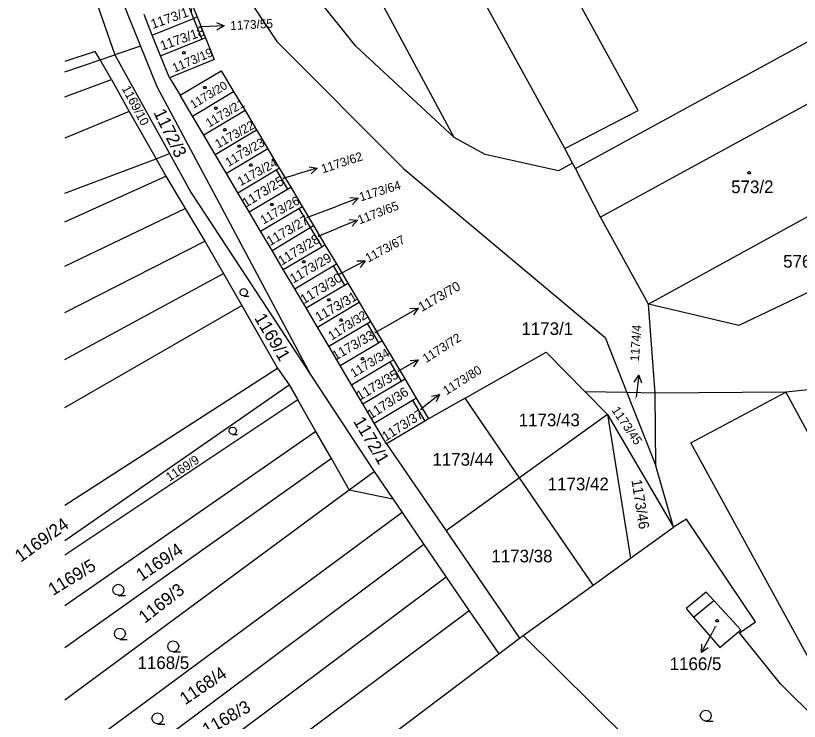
# Model space of a CAD drawing. Extents: x -621797 to -620972, y -1175539 to -1174697.
# Drawn here: x -621796.9 to -621691.5, y -1174979.5 to -1174884.6 of the extents above; entities that cross this region are included whole.
import ezdxf

# ---------------------------------------------------------------- set-up
doc = ezdxf.new("R2010")
doc.units = 0
for name, color, linetype in [('INZ mimo EON - nadz', 7, 'Continuous'), ('Rozvod plynu EON', 7, 'Continuous'), ('SDEL EON', 7, 'Continuous'), ('SDEL EON - popis', 7, 'Continuous'), ('Silnoproud EON', 7, 'Continuous'), ('Silnoproud EON - popis', 7, 'Continuous')]:
    doc.layers.add(name, color=color, linetype=linetype)

msp = doc.modelspace()

# ---------------------------------------------------------------- linework, layer by layer
at = {"layer": 'INZ mimo EON - nadz'}
for p, q in [((-621772.32, -1174886.11), (-621771.91, -1174886.09)), ((-621768.913, -1174885.959), (-621771.91, -1174886.09)), ((-621756.383, -1174905.079), (-621759.26, -1174905.93)), ((-621760.98, -1174906.44), (-621759.26, -1174905.93)), ((-621750.883, -1174909.131), (-621753.69, -1174910.19)), ((-621757.77, -1174911.73), (-621753.69, -1174910.19)), ((-621750.968, -1174912.062), (-621753.74, -1174913.21)), ((-621756.24, -1174914.24), (-621753.74, -1174913.21)), ((-621749.947, -1174917.538), (-621752.61, -1174918.92)), ((-621753.37, -1174919.31), (-621752.61, -1174918.92)), ((-621742.792, -1174923.898), (-621745.4, -1174925.38)), ((-621748.6, -1174927.19), (-621745.4, -1174925.38)), ((-621742.784, -1174930.881), (-621745.4, -1174932.35)), ((-621745.5, -1174932.4), (-621745.4, -1174932.35)), ((-621713.134, -1174932.922), (-621713.5, -1174935.9)), ((-621739.916, -1174935.52), (-621742.27, -1174937.38)), ((-621742.47, -1174937.53), (-621742.27, -1174937.38)), ((-621702.85, -1174966.79), (-621703.28, -1174967.6)), ((-621704.699, -1174970.243), (-621703.28, -1174967.6))]:
    msp.add_line(p, q, dxfattribs=at)
for points in [[(-621769.934, -1174885.503), (-621768.913, -1174885.959), (-621769.89, -1174886.502)], [(-621757.484, -1174904.883), (-621756.383, -1174905.079), (-621757.2, -1174905.842)], [(-621751.995, -1174909.016), (-621750.883, -1174909.131), (-621751.642, -1174909.952)], [(-621752.083, -1174911.983), (-621750.968, -1174912.062), (-621751.701, -1174912.907)], [(-621751.065, -1174917.555), (-621749.947, -1174917.538), (-621750.604, -1174918.443)], [(-621743.908, -1174923.957), (-621742.792, -1174923.898), (-621743.414, -1174924.827)], [(-621743.901, -1174930.935), (-621742.784, -1174930.881), (-621743.411, -1174931.807)], [(-621713.753, -1174933.854), (-621713.134, -1174932.922), (-621712.76, -1174933.976)], [(-621741.011, -1174935.748), (-621739.916, -1174935.52), (-621740.391, -1174936.533)], [(-621703.785, -1174969.599), (-621704.699, -1174970.243), (-621704.666, -1174969.126)]]:
    msp.add_lwpolyline(points, dxfattribs=at)
at = {"layer": 'Rozvod plynu EON'}
for points in [[(-621774.22, -1174889.41), (-621774.13, -1174889.56), (-621774.22, -1174889.71), (-621774.4, -1174889.71), (-621774.49, -1174889.56), (-621774.4, -1174889.41)], [(-621771.42, -1174894.08), (-621771.33, -1174894.23), (-621771.42, -1174894.38), (-621771.6, -1174894.38), (-621771.69, -1174894.23), (-621771.6, -1174894.08)], [(-621769.92, -1174896.87), (-621769.83, -1174897.02), (-621769.92, -1174897.17), (-621770.1, -1174897.17), (-621770.19, -1174897.02), (-621770.1, -1174896.87)], [(-621768.71, -1174899.77), (-621768.62, -1174899.92), (-621768.71, -1174900.07), (-621768.89, -1174900.07), (-621768.98, -1174899.92), (-621768.89, -1174899.77)], [(-621766.8, -1174901.97), (-621766.71, -1174902.12), (-621766.8, -1174902.27), (-621766.98, -1174902.27), (-621767.07, -1174902.12), (-621766.98, -1174901.97)], [(-621765.23, -1174904.51), (-621765.14, -1174904.66), (-621765.23, -1174904.81), (-621765.41, -1174904.81), (-621765.5, -1174904.66), (-621765.41, -1174904.51)], [(-621698.19, -1174905.54), (-621698.1, -1174905.69), (-621698.19, -1174905.84), (-621698.37, -1174905.84), (-621698.46, -1174905.69), (-621698.37, -1174905.54)], [(-621762.38, -1174909.82), (-621762.29, -1174909.97), (-621762.38, -1174910.12), (-621762.56, -1174910.12), (-621762.65, -1174909.97), (-621762.56, -1174909.82)], [(-621758.07, -1174917.52), (-621757.98, -1174917.67), (-621758.07, -1174917.82), (-621758.25, -1174917.82), (-621758.34, -1174917.67), (-621758.25, -1174917.52)], [(-621754.71, -1174922.64), (-621754.62, -1174922.79), (-621754.71, -1174922.94), (-621754.89, -1174922.94), (-621754.98, -1174922.79), (-621754.89, -1174922.64)], [(-621753.06, -1174925.36), (-621752.97, -1174925.51), (-621753.06, -1174925.66), (-621753.24, -1174925.66), (-621753.33, -1174925.51), (-621753.24, -1174925.36)], [(-621750.21, -1174930.56), (-621750.12, -1174930.71), (-621750.21, -1174930.86), (-621750.39, -1174930.86), (-621750.48, -1174930.71), (-621750.39, -1174930.56)], [(-621702.5, -1174965.81), (-621702.41, -1174965.96), (-621702.5, -1174966.11), (-621702.68, -1174966.11), (-621702.77, -1174965.96), (-621702.68, -1174965.81)]]:
    msp.add_lwpolyline(points, close=True, dxfattribs=at)
at = {"layer": 'SDEL EON'}
for points in [[(-621766.25, -1174922.27), (-621766.505, -1174922.203), (-621766.686, -1174922.022), (-621766.752, -1174921.774), (-621766.686, -1174921.526), (-621766.505, -1174921.345), (-621766.257, -1174921.278), (-621766.009, -1174921.345), (-621765.828, -1174921.526), (-621765.761, -1174921.781), (-621765.828, -1174922.036), (-621766.009, -1174922.216), (-621766.263, -1174922.283), (-621765.593, -1174922.283)], [(-621767.74, -1174940.9), (-621767.995, -1174940.833), (-621768.176, -1174940.652), (-621768.242, -1174940.404), (-621768.176, -1174940.156), (-621767.995, -1174939.975), (-621767.747, -1174939.908), (-621767.499, -1174939.975), (-621767.318, -1174940.156), (-621767.251, -1174940.411), (-621767.318, -1174940.666), (-621767.499, -1174940.846), (-621767.753, -1174940.913), (-621767.083, -1174940.913)], [(-621783.12, -1174962.54), (-621783.5, -1174962.44), (-621783.77, -1174962.17), (-621783.87, -1174961.8), (-621783.77, -1174961.43), (-621783.5, -1174961.16), (-621783.13, -1174961.06), (-621782.76, -1174961.16), (-621782.49, -1174961.43), (-621782.39, -1174961.81), (-621782.49, -1174962.19), (-621782.76, -1174962.46), (-621783.14, -1174962.56), (-621782.14, -1174962.56)], [(-621782.91, -1174968.45), (-621783.29, -1174968.35), (-621783.56, -1174968.08), (-621783.66, -1174967.71), (-621783.56, -1174967.34), (-621783.29, -1174967.07), (-621782.92, -1174966.97), (-621782.55, -1174967.07), (-621782.28, -1174967.34), (-621782.18, -1174967.72), (-621782.28, -1174968.1), (-621782.55, -1174968.37), (-621782.93, -1174968.47), (-621781.93, -1174968.47)], [(-621775.74, -1174970.14), (-621776.12, -1174970.04), (-621776.39, -1174969.77), (-621776.49, -1174969.4), (-621776.39, -1174969.03), (-621776.12, -1174968.76), (-621775.75, -1174968.66), (-621775.38, -1174968.76), (-621775.11, -1174969.03), (-621775.01, -1174969.41), (-621775.11, -1174969.79), (-621775.38, -1174970.06), (-621775.76, -1174970.16), (-621774.76, -1174970.16)], [(-621777.85, -1174979.84), (-621778.23, -1174979.74), (-621778.5, -1174979.47), (-621778.6, -1174979.1), (-621778.5, -1174978.73), (-621778.23, -1174978.46), (-621777.86, -1174978.36), (-621777.49, -1174978.46), (-621777.22, -1174978.73), (-621777.12, -1174979.11), (-621777.22, -1174979.49), (-621777.49, -1174979.76), (-621777.87, -1174979.86), (-621776.87, -1174979.86)], [(-621704.12, -1174979.46), (-621704.5, -1174979.36), (-621704.77, -1174979.09), (-621704.87, -1174978.72), (-621704.77, -1174978.35), (-621704.5, -1174978.08), (-621704.13, -1174977.98), (-621703.76, -1174978.08), (-621703.49, -1174978.35), (-621703.39, -1174978.73), (-621703.49, -1174979.11), (-621703.76, -1174979.38), (-621704.14, -1174979.48), (-621703.14, -1174979.48)]]:
    msp.add_lwpolyline(points, dxfattribs=at)
at = {"layer": 'SDEL EON - popis'}
for p, q in [((-621713.24, -1174897.34), (-621756.56, -1174818.04)), ((-621786.26, -1174889.38), (-621790.31, -1174890.72)), ((-621785.59, -1174890.53), (-621786.26, -1174889.38)), ((-621683.62, -1174892.74), (-621718.27, -1174911.66)), ((-621723.06, -1174902.46), (-621713.24, -1174897.34)), ((-621706.15, -1174942.05), (-621693.38, -1174935.2)), ((-621693.38, -1174935.2), (-621666.02, -1174985.69)), ((-621688.4, -1174974.48), (-621706.15, -1174942.05)), ((-621752.08, -1174948.35), (-621746.22, -1174949.57)), ((-621705.76, -1174965.48), (-621703.03, -1174963.24))]:
    msp.add_line(p, q, dxfattribs=at)
at = {"layer": 'Silnoproud EON'}
for p, q in [((-621723.06, -1174902.46), (-621766.48, -1174823.5)), ((-621737.97, -1174900.96), (-621773.9, -1174834.07)), ((-621790.31, -1174863.397), (-621780.14, -1174888.68)), ((-621790.31, -1174870.521), (-621783.6, -1174889.85)), ((-621772.95, -1174871.4), (-621761.8, -1174888.04)), ((-621751.2, -1174888.69), (-621762.62, -1174874.29)), ((-621774.11, -1174882.15), (-621773, -1174884.93)), ((-621773.66, -1174881.96), (-621772.54, -1174884.74)), ((-621778.56, -1174887.19), (-621779.67, -1174884.4)), ((-621778.56, -1174887.19), (-621773, -1174884.93)), ((-621773, -1174884.93), (-621772.54, -1174884.74)), ((-621773, -1174884.93), (-621771.88, -1174887.72)), ((-621772.54, -1174884.74), (-621771.42, -1174887.53)), ((-621721.67, -1174905.13), (-621687.14, -1174886.26)), ((-621777.44, -1174889.97), (-621778.56, -1174887.19)), ((-621777.44, -1174889.97), (-621771.88, -1174887.72)), ((-621771.88, -1174887.72), (-621771.42, -1174887.53)), ((-621771.42, -1174887.53), (-621770.24, -1174890.46)), ((-621780.14, -1174888.68), (-621783.6, -1174889.85)), ((-621780.14, -1174888.68), (-621777.95, -1174894.12)), ((-621761.8, -1174888.04), (-621744.73, -1174905.18)), ((-621737.97, -1174900.96), (-621751.2, -1174888.69)), ((-621785.59, -1174890.53), (-621783.6, -1174889.85)), ((-621783.6, -1174889.85), (-621776.23, -1174903.12)), ((-621790.31, -1174892.134), (-621785.59, -1174890.53)), ((-621784.06, -1174893.17), (-621785.59, -1174890.53)), ((-621776.26, -1174892.92), (-621777.44, -1174889.97)), ((-621770.24, -1174890.46), (-621776.26, -1174892.92)), ((-621774.82, -1174895.27), (-621769.28, -1174891.97)), ((-621769.28, -1174891.97), (-621767.62, -1174894.77)), ((-621776.26, -1174892.92), (-621774.82, -1174895.27)), ((-621790.31, -1174895.476), (-621784.06, -1174893.17)), ((-621784.06, -1174893.17), (-621781.69, -1174897.47)), ((-621777.95, -1174894.12), (-621769.94, -1174909.12)), ((-621773.16, -1174898.07), (-621767.62, -1174894.77)), ((-621767.62, -1174894.77), (-621766.08, -1174897.34)), ((-621773.16, -1174898.07), (-621774.82, -1174895.27)), ((-621781.69, -1174897.47), (-621790.31, -1174901.046)), ((-621781.69, -1174897.47), (-621778.06, -1174903.81)), ((-621771.64, -1174900.65), (-621773.16, -1174898.07)), ((-621766.08, -1174897.34), (-621771.64, -1174900.65)), ((-621766.08, -1174897.34), (-621764.55, -1174899.92)), ((-621770.11, -1174903.23), (-621764.55, -1174899.92)), ((-621764.55, -1174899.92), (-621763.01, -1174902.5)), ((-621770.11, -1174903.23), (-621771.64, -1174900.65)), ((-621733.78, -1174903.26), (-621737.97, -1174900.96)), ((-621763.01, -1174902.5), (-621768.58, -1174905.81)), ((-621763.01, -1174902.5), (-621761.48, -1174905.08)), ((-621722.05, -1174904.4), (-621723.06, -1174902.46)), ((-621778.06, -1174903.81), (-621776.23, -1174903.12)), ((-621776.23, -1174903.12), (-621773.32, -1174908.38)), ((-621768.58, -1174905.81), (-621770.11, -1174903.23)), ((-621723.95, -1174905.43), (-621733.78, -1174903.26)), ((-621790.31, -1174908.448), (-621778.06, -1174903.81)), ((-621778.06, -1174903.81), (-621776.73, -1174906.14)), ((-621722.05, -1174904.4), (-621723.95, -1174905.43)), ((-621721.67, -1174905.13), (-621722.05, -1174904.4)), ((-621677.24, -1174904.34), (-621711.84, -1174923.39)), ((-621767.05, -1174908.39), (-621761.89, -1174905.33)), ((-621761.89, -1174905.33), (-621761.48, -1174905.08)), ((-621761.89, -1174905.33), (-621760.37, -1174907.91)), ((-621761.48, -1174905.08), (-621759.95, -1174907.66)), ((-621744.73, -1174905.18), (-621717.67, -1174927.85)), ((-621718.27, -1174911.66), (-621721.67, -1174905.13)), ((-621790.31, -1174912.295), (-621776.73, -1174906.14)), ((-621776.73, -1174906.14), (-621774.16, -1174910.52)), ((-621767.05, -1174908.39), (-621768.58, -1174905.81)), ((-621760.37, -1174907.91), (-621759.95, -1174907.66)), ((-621759.95, -1174907.66), (-621758.41, -1174910.24)), ((-621773.32, -1174908.38), (-621757.24, -1174932.92)), ((-621765.52, -1174910.97), (-621767.05, -1174908.39)), ((-621765.52, -1174910.97), (-621760.37, -1174907.91)), ((-621769.94, -1174909.12), (-621757.24, -1174932.92)), ((-621790.31, -1174918.28), (-621774.16, -1174910.52)), ((-621774.16, -1174910.52), (-621771.5, -1174914.91)), ((-621763.99, -1174913.56), (-621765.52, -1174910.97)), ((-621763.99, -1174913.56), (-621758.84, -1174910.49)), ((-621758.84, -1174910.49), (-621758.41, -1174910.24)), ((-621758.84, -1174910.49), (-621757.31, -1174913.07)), ((-621758.41, -1174910.24), (-621756.88, -1174912.81)), ((-621711.84, -1174923.39), (-621718.27, -1174911.66)), ((-621762.46, -1174916.14), (-621757.31, -1174913.07)), ((-621757.31, -1174913.07), (-621756.88, -1174912.81)), ((-621757.31, -1174913.07), (-621755.78, -1174915.65)), ((-621756.88, -1174912.81), (-621755.34, -1174915.39)), ((-621762.46, -1174916.14), (-621763.99, -1174913.56)), ((-621790.31, -1174924.516), (-621771.5, -1174914.91)), ((-621771.5, -1174914.91), (-621768.97, -1174919.27)), ((-621676.24, -1174915.04), (-621699.69, -1174926.23)), ((-621760.94, -1174918.72), (-621762.46, -1174916.14)), ((-621760.94, -1174918.72), (-621755.78, -1174915.65)), ((-621755.78, -1174915.65), (-621755.34, -1174915.39)), ((-621755.34, -1174915.39), (-621753.81, -1174917.97)), ((-621759.41, -1174921.3), (-621754.25, -1174918.23)), ((-621754.25, -1174918.23), (-621753.81, -1174917.97)), ((-621754.25, -1174918.23), (-621752.72, -1174920.81)), ((-621753.81, -1174917.97), (-621752.28, -1174920.55)), ((-621790.31, -1174930.838), (-621768.97, -1174919.27)), ((-621768.97, -1174919.27), (-621766.52, -1174923.57)), ((-621759.41, -1174921.3), (-621760.94, -1174918.72)), ((-621757.88, -1174923.88), (-621759.41, -1174921.3)), ((-621757.88, -1174923.88), (-621752.72, -1174920.81)), ((-621752.72, -1174920.81), (-621752.28, -1174920.55)), ((-621752.28, -1174920.55), (-621750.74, -1174923.13)), ((-621790.31, -1174937.274), (-621766.52, -1174923.57)), ((-621766.52, -1174923.57), (-621761.71, -1174932)), ((-621756.35, -1174926.46), (-621751.19, -1174923.39)), ((-621751.19, -1174923.39), (-621750.74, -1174923.13)), ((-621750.74, -1174923.13), (-621749.21, -1174925.7)), ((-621699.69, -1174926.23), (-621711.84, -1174923.39)), ((-621710.94, -1174935.35), (-621711.84, -1174923.39)), ((-621756.35, -1174926.46), (-621757.88, -1174923.88)), ((-621749.67, -1174925.98), (-621749.21, -1174925.7)), ((-621749.21, -1174925.7), (-621747.67, -1174928.28)), ((-621754.82, -1174929.04), (-621756.35, -1174926.46)), ((-621754.82, -1174929.04), (-621749.67, -1174925.98)), ((-621749.67, -1174925.98), (-621748.14, -1174928.56)), ((-621717.67, -1174927.85), (-621714.75, -1174935.27)), ((-621753.29, -1174931.63), (-621748.14, -1174928.56)), ((-621748.14, -1174928.56), (-621747.67, -1174928.28)), ((-621747.67, -1174928.28), (-621746.14, -1174930.86)), ((-621753.29, -1174931.63), (-621754.82, -1174929.04)), ((-621736.5, -1174936.03), (-621725.58, -1174929.84)), ((-621725.58, -1174929.84), (-621720.37, -1174935.15)), ((-621746.61, -1174931.14), (-621746.14, -1174930.86)), ((-621746.14, -1174930.86), (-621744.61, -1174933.44)), ((-621790.31, -1174950.409), (-621761.71, -1174932)), ((-621761.71, -1174932), (-621760.16, -1174934.22)), ((-621751.77, -1174934.21), (-621753.29, -1174931.63)), ((-621751.77, -1174934.21), (-621746.61, -1174931.14)), ((-621746.61, -1174931.14), (-621745.08, -1174933.72)), ((-621757.24, -1174932.92), (-621748.74, -1174945.88)), ((-621750.24, -1174936.79), (-621745.08, -1174933.72)), ((-621745.08, -1174933.72), (-621744.61, -1174933.44)), ((-621744.61, -1174933.44), (-621743.07, -1174936.02)), ((-621790.31, -1174955.158), (-621760.16, -1174934.22)), ((-621760.16, -1174934.22), (-621759.01, -1174936.23)), ((-621750.24, -1174936.79), (-621751.77, -1174934.21)), ((-621714.75, -1174935.27), (-621720.37, -1174935.15)), ((-621720.37, -1174935.15), (-621717.33, -1174938.24)), ((-621693.38, -1174935.2), (-621710.94, -1174935.35)), ((-621688.39, -1174934.69), (-621693.38, -1174935.2)), ((-621759.01, -1174936.23), (-621790.31, -1174957.145)), ((-621756.56, -1174940.51), (-621759.01, -1174936.23)), ((-621748.71, -1174939.37), (-621743.55, -1174936.3)), ((-621743.55, -1174936.3), (-621743.07, -1174936.02)), ((-621743.55, -1174936.3), (-621741.9, -1174939.1)), ((-621743.07, -1174936.02), (-621741.41, -1174938.81)), ((-621736.5, -1174936.03), (-621741.41, -1174938.81)), ((-621729.17, -1174946.75), (-621736.5, -1174936.03)), ((-621710.94, -1174935.35), (-621714.75, -1174935.27)), ((-621714.75, -1174935.27), (-621710.86, -1174945.13)), ((-621710.86, -1174945.13), (-621710.94, -1174935.35)), ((-621748.71, -1174939.37), (-621750.24, -1174936.79)), ((-621717.33, -1174938.24), (-621729.17, -1174946.75)), ((-621717.33, -1174938.24), (-621708.48, -1174953.39)), ((-621717.33, -1174938.24), (-621714.25, -1174957.55)), ((-621747.05, -1174942.17), (-621748.71, -1174939.37)), ((-621741.9, -1174939.1), (-621747.05, -1174942.17)), ((-621741.41, -1174938.81), (-621741.9, -1174939.1)), ((-621756.56, -1174940.51), (-621790.31, -1174963.977)), ((-621754.47, -1174944.16), (-621756.56, -1174940.51)), ((-621747.05, -1174942.17), (-621739.05, -1174953.85)), ((-621754.47, -1174944.16), (-621790.31, -1174969.598)), ((-621752.08, -1174948.35), (-621754.47, -1174944.16)), ((-621708.48, -1174953.39), (-621710.86, -1174945.13)), ((-621752.08, -1174948.35), (-621748.74, -1174945.88)), ((-621748.74, -1174945.88), (-621746.22, -1174949.57)), ((-621729.17, -1174946.75), (-621739.05, -1174953.85)), ((-621719.29, -1174961.18), (-621729.17, -1174946.75)), ((-621790.31, -1174976.603), (-621752.08, -1174948.35)), ((-621746.22, -1174949.57), (-621744.96, -1174951.42)), ((-621744.96, -1174951.42), (-621790.31, -1174984.913)), ((-621744.96, -1174951.42), (-621742.03, -1174955.71)), ((-621706.74, -1174952.32), (-621708.48, -1174953.39)), ((-621697.46, -1174966.12), (-621706.74, -1174952.32)), ((-621739.05, -1174953.85), (-621729.18, -1174968.32)), ((-621714.25, -1174957.55), (-621708.48, -1174953.39)), ((-621742.03, -1174955.71), (-621790.31, -1174991.795)), ((-621742.03, -1174955.71), (-621739.05, -1174960.08)), ((-621719.29, -1174961.18), (-621714.25, -1174957.55)), ((-621739.05, -1174960.08), (-621790.31, -1174998.498)), ((-621739.05, -1174960.08), (-621735.95, -1174964.61)), ((-621728.68, -1174967.95), (-621719.29, -1174961.18)), ((-621704.06, -1174962.11), (-621706.77, -1174964.31)), ((-621703.03, -1174963.24), (-621704.06, -1174962.11)), ((-621699.4, -1174967.2), (-621703.03, -1174963.24)), ((-621735.95, -1174964.61), (-621790.31, -1175005.233)), ((-621735.95, -1174964.61), (-621731.98, -1174970.42)), ((-621706.77, -1174964.31), (-621705.76, -1174965.48)), ((-621705.76, -1174965.48), (-621702.25, -1174969.58)), ((-621699.58, -1174967.59), (-621697.46, -1174966.12)), ((-621702.25, -1174969.58), (-621699.4, -1174967.2)), ((-621694.08, -1174974.46), (-621699.58, -1174967.59)), ((-621731.98, -1174970.42), (-621729.18, -1174968.32)), ((-621729.18, -1174968.32), (-621728.68, -1174967.95)), ((-621691.74, -1175004.45), (-621728.68, -1174967.95)), ((-621787.64, -1175012.33), (-621731.98, -1174970.42)), ((-621677.59, -1174990.81), (-621694.08, -1174974.46))]:
    msp.add_line(p, q, dxfattribs=at)

# ---------------------------------------------------------------- texts
at = {"layer": 'INZ mimo EON - nadz'}
for s, height, rotation, p in [('1173/55', 1.19, 3.03668, (-621768.045, -1174886.508)), ('1173/62', 1.19, 18.16276, (-621755.618, -1174905.784)), ('1173/64', 1.19, 17.18873, (-621750.524, -1174909.561)), ('1173/65', 1.19, 20.97026, (-621750.671, -1174912.655)), ('1173/67', 1.19, 28.13223, (-621749.515, -1174917.801)), ('1173/70', 1.28, 30.02299, (-621742.335, -1174924.443)), ('1174/4', 1.2, 86.00096, (-621713.121, -1174931.093)), ('1173/72', 1.19, 32.71589, (-621741.731, -1174931.317)), ('1173/80', 1.19, 32.42941, (-621738.991, -1174935.643))]:
    msp.add_text(s, height=height, rotation=rotation, dxfattribs=at).set_placement(p)
msp.add_text('1166/5', height=1.7, dxfattribs=at).set_placement((-621708.983, -1174972.6))
at = {"layer": 'Silnoproud EON - popis'}
for s, height, rotation, p in [('1173/17', 1.28, 19.42327, (-621778.5, -1174886.365)), ('1173/18', 1.28, 19.76704, (-621777.237, -1174889.276)), ('1173/55', 0.1, 293.58357, (-621772.42, -1174885.881)), ('1173/19', 1.19, 23.49127, (-621775.558, -1174892.24)), ('1169/10', 1.2, 297.88076, (-621782.7, -1174894.355)), ('1173/20', 1.14, 31.1689, (-621773.056, -1174897.13)), ('1173/21', 1.19, 30.93972, (-621770.934, -1174899.659)), ('1172/3', 1.7, 296.10459, (-621778.437, -1174897.593)), ('1173/22', 1.19, 28.87707, (-621769.719, -1174902.447)), ('1173/23', 1.2, 30.59595, (-621768.311, -1174904.929)), ('1173/24', 1.2, 28.81978, (-621766.687, -1174907.516)), ('1173/25', 1.28, 31.79916, (-621765.971, -1174910.429)), ('1173/62', 0.1, 301.03202, (-621761.108, -1174906.226)), ('1173/26', 1.19, 29.79381, (-621763.611, -1174912.683)), ('1173/27', 1.28, 30.30947, (-621762.728, -1174915.574)), ('1173/64', 0.1, 296.04729, (-621757.878, -1174911.51)), ('1173/28', 1.28, 31.34079, (-621761.167, -1174918.207)), ('1173/65', 0.1, 299.25586, (-621756.361, -1174914.024)), ('1173/29', 1.27, 30.36676, (-621759.611, -1174920.62)), ('1173/30', 1.28, 31.34079, (-621758.18, -1174923.405)), ('1173/67', 0.1, 302.17794, (-621753.499, -1174919.105)), ('1173/31', 1.27, 29.8511, (-621756.198, -1174925.781)), ('1169/1', 1.7, 300.57366, (-621764.9, -1174925.228)), ('1173/32', 1.2, 32.544, (-621754.436, -1174928.291)), ('1173/33', 1.28, 29.67921, (-621753.927, -1174930.997)), ('1173/70', 0.1, 304.35518, (-621748.738, -1174926.989)), ('1173/34', 1.2, 31.2262, (-621751.483, -1174933.296)), ('1173/35', 1.28, 30.71054, (-621750.641, -1174936.372)), ('1173/72', 0.1, 297.59428, (-621745.614, -1174932.181)), ('1173/36', 1.28, 33.17426, (-621749.148, -1174938.901)), ('1174/4', 0.1, 294.32842, (-621713.71, -1174935.951)), ('1173/80', 0.1, 303.32386, (-621742.606, -1174937.323)), ('1173/45', 1.2, 304.18329, (-621716.844, -1174937.649)), ('1173/37', 1.28, 32.65859, (-621747.168, -1174941.86)), ('1172/1', 1.7, 300.57366, (-621751.59, -1174939.128)), ('1169/9', 1.2, 32.37212, (-621776.256, -1174947.272)), ('1173/46', 1.4, 278.97315, (-621714.13, -1174947.039)), ('1169/24', 1.7, 35.98175, (-621796.272, -1174958.179)), ('1169/4', 1.7, 34.20558, (-621780.015, -1174960.719)), ('1169/5', 1.7, 31.51268, (-621791.905, -1174962.645)), ('1169/3', 1.7, 37.81521, (-621779.57, -1174966.389)), ('1168/4', 1.7, 34.20558, (-621774.135, -1174977.349)), ('1168/3', 1.7, 29.67921, (-621771.209, -1174981.496))]:
    msp.add_text(s, height=height, rotation=rotation, dxfattribs=at).set_placement(p)
for s, height, p in [('573/2', 1.7, (-621700.713, -1174908.44)), ('576/2', 1.7, (-621693.723, -1174918.47)), ('1173/1', 1.7, (-621728.917, -1174927.52)), ('1173/43', 1.7, (-621729.287, -1174939.8)), ('1173/44', 1.7, (-621740.887, -1174945.11)), ('1173/42', 1.7, (-621725.387, -1174948.41)), ('1173/38', 1.7, (-621732.957, -1174958.11)), ('1166/5', 0.1, (-621703.054, -1174966.79)), ('1168/5', 1.7, (-621780.547, -1174972.46))]:
    msp.add_text(s, height=height, dxfattribs=at).set_placement(p)

doc.saveas('drawing.dxf')
